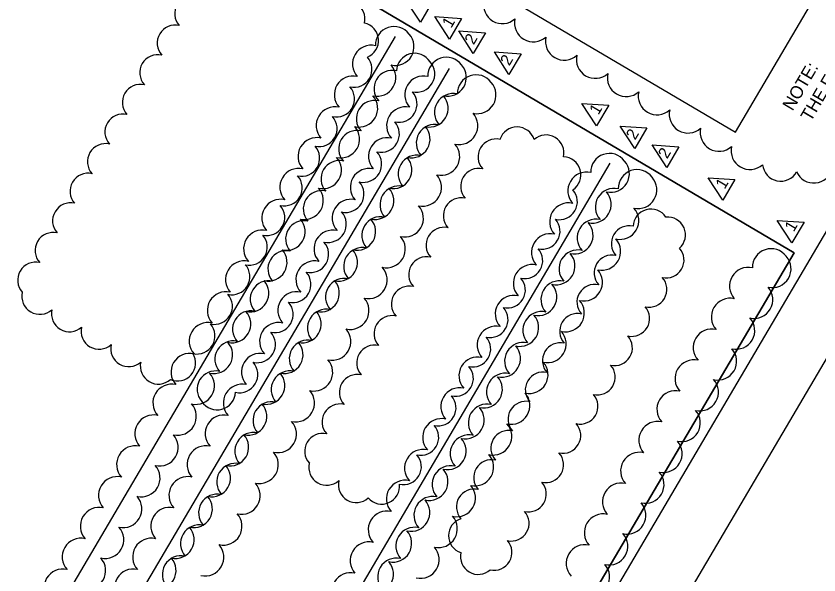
# Model space of a CAD drawing. Extents: x 12 to 1151523, y -64 to 610812.
# Drawn here: x 1151171.991 to 1151172.624, y 610616.177 to 610616.617 of the extents above; entities that cross this region are included whole.
import ezdxf

# ---------------------------------------------------------------- set-up
doc = ezdxf.new("R2010")
doc.units = 0
for name, color, linetype in [('ANNOTATION', 7, 'Continuous'), ('BANNOTATION', 7, 'Continuous'), ('BORDER', 7, 'Continuous'), ('DIMENSIONS', 7, 'Continuous'), ('PLOT BOUNDARY', 7, 'Continuous')]:
    doc.layers.add(name, color=color, linetype=linetype)

msp = doc.modelspace()

# ---------------------------------------------------------------- linework, layer by layer
at = {"layer": 'ANNOTATION'}
for p, q in [((1151171.68443, 610615.57233), (1151172.29045, 610616.60119)), ((1151171.72712, 610615.54719), (1151172.33313, 610616.57605)), ((1151171.85385, 610615.47254), (1151172.45987, 610616.5014))]:
    msp.add_line(p, q, dxfattribs=at)
for points in [[(1151172.55849, 610616.52572), (1151173.14334, 610617.51864), (1151172.53973, 610617.87417), (1151171.95488, 610616.88126)], [(1151170.49753, 610616.26298), (1151171.11366, 610617.30901), (1151172.60473, 610616.43074), (1151171.9886, 610615.38471)], [(1151171.9886, 610615.38471), (1151172.60473, 610616.43074), (1151171.11366, 610617.30901), (1151170.49753, 610616.26298)]]:
    msp.add_lwpolyline(points, close=True, dxfattribs=at)
for centre, radius, start, end in [((1151172.13056, 610616.61929), 0.01421, 77.0011, 222.0011), ((1151172.25215, 610616.61496), 0.01421, 347.0011, 132.0011), ((1151172.37476, 610616.62612), 0.01485, 167.0011, 312.0011), ((1151172.37476, 610616.62612), 0.01485, 167.0011, 312.0011), ((1151172.2629, 610616.59791), 0.0142, 292.39822, 77.39822), ((1151172.39916, 610616.61175), 0.01485, 167.0011, 312.0011), ((1151172.39916, 610616.61175), 0.01485, 167.0011, 312.0011), ((1151172.11681, 610616.59594), 0.01421, 77.0011, 222.0011), ((1151172.28941, 610616.59427), 0.01476, 36.35963, 181.35963), ((1151172.29032, 610616.59313), 0.01478, 257.0011, 42.0011), ((1151172.42356, 610616.59738), 0.01485, 167.0011, 312.0011), ((1151172.42356, 610616.59738), 0.01485, 167.0011, 312.0011), ((1151172.27133, 610616.57952), 0.01478, 77.0011, 222.0011), ((1151172.10305, 610616.57259), 0.01421, 77.0011, 222.0011), ((1151172.30564, 610616.57351), 0.0144, 32.75613, 177.75613), ((1151172.44796, 610616.58301), 0.01485, 167.0011, 312.0011), ((1151172.44796, 610616.58301), 0.01485, 167.0011, 312.0011), ((1151172.25775, 610616.57528), 0.01421, 257.0011, 42.0011), ((1151172.30704, 610616.57165), 0.01441, 257.0011, 42.0011), ((1151172.33065, 610616.56998), 0.01476, 36.35963, 181.35963), ((1151172.27602, 610616.56885), 0.01478, 257.0011, 42.0011), ((1151172.288, 610616.56003), 0.01441, 77.0011, 222.0011), ((1151172.33156, 610616.56884), 0.01478, 257.0011, 42.0011), ((1151172.25702, 610616.55524), 0.01478, 77.0011, 222.0011), ((1151172.31257, 610616.55523), 0.01478, 77.0011, 222.0011), ((1151172.35404, 610616.5562), 0.01476, 36.35963, 181.35963), ((1151172.47236, 610616.56863), 0.01485, 167.0011, 312.0011), ((1151172.47236, 610616.56863), 0.01485, 167.0011, 312.0011), ((1151172.0893, 610616.54924), 0.01421, 77.0011, 222.0011), ((1151172.24399, 610616.55193), 0.01421, 257.0011, 42.0011), ((1151172.35495, 610616.55507), 0.01478, 257.0011, 42.0011), ((1151172.26171, 610616.54456), 0.01478, 257.0011, 42.0011), ((1151172.29309, 610616.54797), 0.01441, 257.0011, 42.0011), ((1151172.31726, 610616.54456), 0.01478, 257.0011, 42.0011), ((1151172.33596, 610616.54145), 0.01478, 77.0011, 222.0011), ((1151172.49676, 610616.55426), 0.01485, 167.0011, 312.0011), ((1151172.49676, 610616.55426), 0.01485, 167.0011, 312.0011), ((1151172.27405, 610616.53634), 0.01441, 77.0011, 222.0011), ((1151172.24272, 610616.53095), 0.01478, 77.0011, 222.0011), ((1151172.29826, 610616.53094), 0.01478, 77.0011, 222.0011), ((1151172.52116, 610616.53989), 0.01485, 167.0011, 312.0011), ((1151172.52116, 610616.53989), 0.01485, 167.0011, 312.0011), ((1151172.07554, 610616.52588), 0.01421, 77.0011, 222.0011), ((1151172.23024, 610616.52857), 0.01421, 257.0011, 42.0011), ((1151172.34064, 610616.53078), 0.01478, 257.0011, 42.0011), ((1151172.24741, 610616.52028), 0.01478, 257.0011, 42.0011), ((1151172.27914, 610616.52428), 0.01441, 257.0011, 42.0011), ((1151172.30295, 610616.52027), 0.01478, 257.0011, 42.0011), ((1151172.32165, 610616.51717), 0.01478, 77.0011, 222.0011), ((1151172.38633, 610616.51574), 0.01411, 17.24342, 162.24342), ((1151172.54556, 610616.52552), 0.01485, 167.0011, 312.0011), ((1151172.54556, 610616.52552), 0.01485, 167.0011, 312.0011), ((1151172.55265, 610616.53034), 0.02161, 183.93653357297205, 183.93653379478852), ((1151172.2601, 610616.51265), 0.01441, 77.0011, 222.0011), ((1151172.40925, 610616.50943), 0.01412, 347.0011, 132.0011), ((1151172.06179, 610616.50253), 0.01421, 77.0011, 222.0011), ((1151172.22841, 610616.50667), 0.01478, 77.0011, 222.0011), ((1151172.28396, 610616.50666), 0.01478, 77.0011, 222.0011), ((1151172.32634, 610616.5065), 0.01478, 257.0011, 42.0011), ((1151172.36972, 610616.50629), 0.01412, 77.0011, 222.0011), ((1151172.21648, 610616.50522), 0.01421, 257.0011, 42.0011), ((1151172.26518, 610616.50059), 0.01441, 257.0011, 42.0011), ((1151172.56996, 610616.51115), 0.01485, 167.0011, 312.0011), ((1151172.56996, 610616.51115), 0.01485, 167.0011, 312.0011), ((1151172.2331, 610616.49599), 0.01478, 257.0011, 42.0011), ((1151172.24615, 610616.48896), 0.01441, 77.0011, 222.0011), ((1151172.28865, 610616.49599), 0.01478, 257.0011, 42.0011), ((1151172.30735, 610616.49288), 0.01478, 77.0011, 222.0011), ((1151172.42256, 610616.49214), 0.01412, 303.19854, 88.19854), ((1151172.45922, 610616.49425), 0.01476, 36.35963, 181.35963), ((1151172.21411, 610616.48238), 0.01478, 77.0011, 222.0011), ((1151172.26965, 610616.48237), 0.01478, 77.0011, 222.0011), ((1151172.35605, 610616.48308), 0.01412, 77.0011, 222.0011), ((1151172.46013, 610616.49312), 0.01478, 257.0011, 42.0011), ((1151172.59423, 610616.50157), 0.01441, 185.78345, 330.78345), ((1151172.59423, 610616.50157), 0.01441, 185.78345, 330.78345), ((1151172.62038, 610616.50051), 0.01484, 203.75334, 346.71427), ((1151172.04803, 610616.47918), 0.01421, 77.0011, 222.0011), ((1151172.20273, 610616.48187), 0.01421, 257.0011, 42.0011), ((1151172.31204, 610616.48221), 0.01478, 257.0011, 42.0011), ((1151172.44113, 610616.4795), 0.01478, 77.0011, 222.0011), ((1151172.48094, 610616.48146), 0.01476, 36.35963, 181.35963), ((1151172.62601, 610616.48509), 0.0214, 153.80626168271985, 153.8062619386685), ((1151172.25123, 610616.47691), 0.01441, 257.0011, 42.0011), ((1151172.48184, 610616.48032), 0.01478, 257.0011, 42.0011), ((1151172.2188, 610616.47171), 0.01478, 257.0011, 42.0011), ((1151172.2322, 610616.46528), 0.01441, 77.0011, 222.0011), ((1151172.27434, 610616.4717), 0.01478, 257.0011, 42.0011), ((1151172.29304, 610616.4686), 0.01478, 77.0011, 222.0011), ((1151172.4198, 610616.47088), 0.01412, 257.0011, 42.0011), ((1151172.44582, 610616.46883), 0.01478, 257.0011, 42.0011), ((1151172.46285, 610616.46671), 0.01478, 77.0011, 222.0011), ((1151172.1998, 610616.45809), 0.01478, 77.0011, 222.0011), ((1151172.25535, 610616.45809), 0.01478, 77.0011, 222.0011), ((1151172.34238, 610616.45988), 0.01412, 77.0011, 222.0011), ((1151172.03428, 610616.45583), 0.01421, 77.0011, 222.0011), ((1151172.18897, 610616.45851), 0.01421, 257.0011, 42.0011), ((1151172.29773, 610616.45793), 0.01478, 257.0011, 42.0011), ((1151172.42683, 610616.45522), 0.01478, 77.0011, 222.0011), ((1151172.46754, 610616.45604), 0.01478, 257.0011, 42.0011), ((1151172.23728, 610616.45322), 0.01441, 257.0011, 42.0011), ((1151172.27874, 610616.44431), 0.01478, 77.0011, 222.0011), ((1151172.49189, 610616.45111), 0.01403, 33.0718, 178.0718), ((1151172.20449, 610616.44742), 0.01478, 257.0011, 42.0011), ((1151172.21824, 610616.44159), 0.01441, 77.0011, 222.0011), ((1151172.26004, 610616.44742), 0.01478, 257.0011, 42.0011), ((1151172.40613, 610616.44768), 0.01412, 257.0011, 42.0011), ((1151172.43152, 610616.44455), 0.01478, 257.0011, 42.0011), ((1151172.44855, 610616.44242), 0.01478, 77.0011, 222.0011), ((1151172.50518, 610616.44483), 0.01401, 311.28305, 96.28305), ((1151172.02052, 610616.43247), 0.01421, 77.0011, 222.0011), ((1151172.1855, 610616.43381), 0.01478, 77.0011, 222.0011), ((1151172.24104, 610616.4338), 0.01478, 77.0011, 222.0011), ((1151172.32872, 610616.43667), 0.01412, 77.0011, 222.0011), ((1151172.47472, 610616.43792), 0.01402, 77.0011, 222.0011), ((1151172.17522, 610616.43516), 0.01421, 257.0011, 42.0011), ((1151172.28343, 610616.43364), 0.01478, 257.0011, 42.0011), ((1151172.41252, 610616.43093), 0.01478, 77.0011, 222.0011), ((1151172.45324, 610616.43175), 0.01478, 257.0011, 42.0011), ((1151172.22333, 610616.42953), 0.01441, 257.0011, 42.0011), ((1151172.26443, 610616.42003), 0.01478, 77.0011, 222.0011), ((1151172.39247, 610616.42447), 0.01412, 257.0011, 42.0011), ((1151172.504, 610616.42492), 0.01402, 257.0011, 42.0011), ((1151172.5867, 610616.41916), 0.01476, 36.35963, 181.35963), ((1151172.19019, 610616.42314), 0.01478, 257.0011, 42.0011), ((1151172.20429, 610616.4179), 0.01441, 77.0011, 222.0011), ((1151172.24573, 610616.42313), 0.01478, 257.0011, 42.0011), ((1151172.31505, 610616.41347), 0.01412, 77.0011, 222.0011), ((1151172.41721, 610616.42026), 0.01478, 257.0011, 42.0011), ((1151172.43424, 610616.41814), 0.01478, 77.0011, 222.0011), ((1151172.46114, 610616.41487), 0.01402, 77.0011, 222.0011), ((1151172.58761, 610616.41802), 0.01478, 257.0011, 42.0011), ((1151172.00677, 610616.40912), 0.01421, 77.0011, 222.0011), ((1151172.1712, 610616.40952), 0.01478, 77.0011, 222.0011), ((1151172.16146, 610616.41181), 0.01421, 257.0011, 42.0011), ((1151172.22674, 610616.40952), 0.01478, 77.0011, 222.0011), ((1151172.39822, 610616.40665), 0.01478, 77.0011, 222.0011), ((1151172.20938, 610616.40584), 0.01441, 257.0011, 42.0011), ((1151172.26912, 610616.40936), 0.01478, 257.0011, 42.0011), ((1151172.43893, 610616.40747), 0.01478, 257.0011, 42.0011), ((1151172.56862, 610616.40441), 0.01478, 77.0011, 222.0011), ((1151172.17588, 610616.39885), 0.01478, 257.0011, 42.0011), ((1151172.19034, 610616.39422), 0.01441, 77.0011, 222.0011), ((1151172.23143, 610616.39885), 0.01478, 257.0011, 42.0011), ((1151172.25013, 610616.39574), 0.01478, 77.0011, 222.0011), ((1151172.3788, 610616.40127), 0.01412, 257.0011, 42.0011), ((1151172.41994, 610616.39385), 0.01478, 77.0011, 222.0011), ((1151172.49043, 610616.40188), 0.01402, 257.0011, 42.0011), ((1151172.30138, 610616.39026), 0.01412, 77.0011, 222.0011), ((1151172.40291, 610616.39597), 0.01478, 257.0011, 42.0011), ((1151172.44757, 610616.39183), 0.01402, 77.0011, 222.0011), ((1151172.57331, 610616.39374), 0.01478, 257.0011, 42.0011), ((1151172.01005, 610616.39642), 0.01421, 167.0011, 312.0011), ((1151172.15689, 610616.38524), 0.01478, 77.0011, 222.0011), ((1151172.14771, 610616.38846), 0.01421, 257.0011, 42.0011), ((1151172.21244, 610616.38523), 0.01478, 77.0011, 222.0011), ((1151172.38392, 610616.38236), 0.01478, 77.0011, 222.0011), ((1151172.19542, 610616.38216), 0.01441, 257.0011, 42.0011), ((1151172.25482, 610616.38507), 0.01478, 257.0011, 42.0011), ((1151172.42463, 610616.38318), 0.01478, 257.0011, 42.0011), ((1151172.55432, 610616.38012), 0.01478, 77.0011, 222.0011), ((1151172.0334, 610616.38266), 0.01421, 167.0011, 312.0011), ((1151172.16158, 610616.37457), 0.01478, 257.0011, 42.0011), ((1151172.17639, 610616.37053), 0.01441, 77.0011, 222.0011), ((1151172.21712, 610616.37456), 0.01478, 257.0011, 42.0011), ((1151172.23582, 610616.37146), 0.01478, 77.0011, 222.0011), ((1151172.36513, 610616.37806), 0.01412, 257.0011, 42.0011), ((1151172.40563, 610616.36957), 0.01478, 77.0011, 222.0011), ((1151172.47685, 610616.37883), 0.01402, 257.0011, 42.0011), ((1151172.28771, 610616.36706), 0.01412, 77.0011, 222.0011), ((1151172.3886, 610616.37169), 0.01478, 257.0011, 42.0011), ((1151172.434, 610616.36878), 0.01402, 77.0011, 222.0011), ((1151172.559, 610616.36945), 0.01478, 257.0011, 42.0011), ((1151172.05676, 610616.36891), 0.01421, 167.0011, 312.0011), ((1151172.14259, 610616.36095), 0.01478, 77.0011, 222.0011), ((1151172.13395, 610616.3651), 0.01421, 257.0011, 42.0011), ((1151172.19813, 610616.36095), 0.01478, 77.0011, 222.0011), ((1151172.24051, 610616.36078), 0.01478, 257.0011, 42.0011), ((1151172.36961, 610616.35808), 0.01478, 77.0011, 222.0011), ((1151172.54001, 610616.35584), 0.01478, 77.0011, 222.0011), ((1151172.18147, 610616.35847), 0.01441, 257.0011, 42.0011), ((1151172.35146, 610616.35486), 0.01412, 257.0011, 42.0011), ((1151172.41032, 610616.3589), 0.01478, 257.0011, 42.0011), ((1151172.46328, 610616.35579), 0.01402, 257.0011, 42.0011), ((1151172.08011, 610616.35515), 0.01421, 167.0011, 312.0011), ((1151172.14727, 610616.35028), 0.01478, 257.0011, 42.0011), ((1151172.16243, 610616.34684), 0.01441, 77.0011, 222.0011), ((1151172.20282, 610616.35028), 0.01478, 257.0011, 42.0011), ((1151172.22152, 610616.34717), 0.01478, 77.0011, 222.0011), ((1151172.27404, 610616.34385), 0.01412, 77.0011, 222.0011), ((1151172.39133, 610616.34528), 0.01478, 77.0011, 222.0011), ((1151172.42042, 610616.34574), 0.01402, 77.0011, 222.0011), ((1151172.12828, 610616.33667), 0.01478, 77.0011, 222.0011), ((1151172.18383, 610616.33666), 0.01478, 77.0011, 222.0011), ((1151172.3743, 610616.3474), 0.01478, 257.0011, 42.0011), ((1151172.5447, 610616.34517), 0.01478, 257.0011, 42.0011), ((1151172.11864, 610616.34385), 0.0142, 246.44677, 31.44677), ((1151172.22621, 610616.3365), 0.01478, 257.0011, 42.0011), ((1151172.35531, 610616.33379), 0.01478, 77.0011, 222.0011), ((1151172.52571, 610616.33155), 0.01478, 77.0011, 222.0011), ((1151172.10346, 610616.3414), 0.01421, 167.0011, 312.0011), ((1151172.16752, 610616.33478), 0.01441, 257.0011, 42.0011), ((1151172.33779, 610616.33165), 0.01412, 257.0011, 42.0011), ((1151172.39602, 610616.33461), 0.01478, 257.0011, 42.0011), ((1151172.44971, 610616.33274), 0.01402, 257.0011, 42.0011), ((1151172.13297, 610616.326), 0.01478, 257.0011, 42.0011), ((1151172.14848, 610616.32315), 0.01441, 77.0011, 222.0011), ((1151172.18851, 610616.32599), 0.01478, 257.0011, 42.0011), ((1151172.20722, 610616.32289), 0.01478, 77.0011, 222.0011), ((1151172.26038, 610616.32065), 0.01412, 77.0011, 222.0011), ((1151172.35999, 610616.32312), 0.01478, 257.0011, 42.0011), ((1151172.37702, 610616.321), 0.01478, 77.0011, 222.0011), ((1151172.40685, 610616.32269), 0.01402, 77.0011, 222.0011), ((1151172.11398, 610616.31238), 0.01478, 77.0011, 222.0011), ((1151172.16952, 610616.31238), 0.01478, 77.0011, 222.0011), ((1151172.53039, 610616.32088), 0.01478, 257.0011, 42.0011), ((1151172.14988, 610616.3213), 0.0144, 212.75613, 357.75613), ((1151172.2119, 610616.31221), 0.01478, 257.0011, 42.0011), ((1151172.341, 610616.30951), 0.01478, 77.0011, 222.0011), ((1151172.38171, 610616.31033), 0.01478, 257.0011, 42.0011), ((1151172.5114, 610616.30727), 0.01478, 77.0011, 222.0011), ((1151172.32412, 610616.30845), 0.01412, 257.0011, 42.0011), ((1151172.39327, 610616.29965), 0.01402, 77.0011, 222.0011), ((1151172.43613, 610616.3097), 0.01402, 257.0011, 42.0011), ((1151172.11867, 610616.30171), 0.01478, 257.0011, 42.0011), ((1151172.17421, 610616.30171), 0.01478, 257.0011, 42.0011), ((1151172.19291, 610616.2986), 0.01478, 77.0011, 222.0011), ((1151172.24671, 610616.29744), 0.01412, 77.0011, 222.0011), ((1151172.34569, 610616.29883), 0.01478, 257.0011, 42.0011), ((1151172.36272, 610616.29671), 0.01478, 77.0011, 222.0011), ((1151172.09967, 610616.2881), 0.01478, 77.0011, 222.0011), ((1151172.15522, 610616.28809), 0.01478, 77.0011, 222.0011), ((1151172.51609, 610616.2966), 0.01478, 257.0011, 42.0011), ((1151172.1976, 610616.28793), 0.01478, 257.0011, 42.0011), ((1151172.31046, 610616.28524), 0.01412, 257.0011, 42.0011), ((1151172.3267, 610616.28522), 0.01478, 77.0011, 222.0011), ((1151172.36741, 610616.28604), 0.01478, 257.0011, 42.0011), ((1151172.42256, 610616.28666), 0.01402, 257.0011, 42.0011), ((1151172.4971, 610616.28298), 0.01478, 77.0011, 222.0011), ((1151172.17861, 610616.27432), 0.01478, 77.0011, 222.0011), ((1151172.23304, 610616.27424), 0.01412, 77.0011, 222.0011), ((1151172.3797, 610616.2766), 0.01402, 77.0011, 222.0011), ((1151172.10436, 610616.27743), 0.01478, 257.0011, 42.0011), ((1151172.15991, 610616.27742), 0.01478, 257.0011, 42.0011), ((1151172.33139, 610616.27455), 0.01478, 257.0011, 42.0011), ((1151172.34842, 610616.27243), 0.01478, 77.0011, 222.0011), ((1151172.50179, 610616.27231), 0.01478, 257.0011, 42.0011), ((1151172.08537, 610616.26381), 0.01478, 77.0011, 222.0011), ((1151172.14091, 610616.26381), 0.01478, 77.0011, 222.0011), ((1151172.31239, 610616.26093), 0.01478, 77.0011, 222.0011), ((1151172.18329, 610616.26364), 0.01478, 257.0011, 42.0011), ((1151172.29679, 610616.26204), 0.01412, 257.0011, 42.0011), ((1151172.3531, 610616.26176), 0.01478, 257.0011, 42.0011), ((1151172.40899, 610616.26361), 0.01402, 257.0011, 42.0011), ((1151172.48279, 610616.2587), 0.01478, 77.0011, 222.0011), ((1151172.09006, 610616.25314), 0.01478, 257.0011, 42.0011), ((1151172.1456, 610616.25313), 0.01478, 257.0011, 42.0011), ((1151172.1643, 610616.25003), 0.01478, 77.0011, 222.0011), ((1151172.2363, 610616.26161), 0.01412, 167.0011, 312.0011), ((1151172.33411, 610616.24814), 0.01478, 77.0011, 222.0011), ((1151172.36613, 610616.25356), 0.01402, 77.0011, 222.0011), ((1151172.31708, 610616.25026), 0.01478, 257.0011, 42.0011), ((1151172.48748, 610616.24803), 0.01478, 257.0011, 42.0011), ((1151172.07106, 610616.23953), 0.01478, 77.0011, 222.0011), ((1151172.12661, 610616.23952), 0.01478, 77.0011, 222.0011), ((1151172.25951, 610616.24795), 0.01412, 167.0011, 312.0011), ((1151172.29809, 610616.23665), 0.01478, 77.0011, 222.0011), ((1151172.16899, 610616.23936), 0.01478, 257.0011, 42.0011), ((1151172.27958, 610616.24675), 0.01412, 221.20772, 6.20772), ((1151172.3388, 610616.23747), 0.01478, 257.0011, 42.0011), ((1151172.35255, 610616.23052), 0.01402, 77.0011, 222.0011), ((1151172.39541, 610616.24057), 0.01402, 257.0011, 42.0011), ((1151172.46849, 610616.23441), 0.01478, 77.0011, 222.0011), ((1151172.07575, 610616.22886), 0.01478, 257.0011, 42.0011), ((1151172.1313, 610616.22885), 0.01478, 257.0011, 42.0011), ((1151172.15, 610616.22574), 0.01478, 77.0011, 222.0011), ((1151172.31981, 610616.22386), 0.01478, 77.0011, 222.0011), ((1151172.30278, 610616.22598), 0.01478, 257.0011, 42.0011), ((1151172.47318, 610616.22374), 0.01478, 257.0011, 42.0011), ((1151172.05676, 610616.21524), 0.01478, 77.0011, 222.0011), ((1151172.1123, 610616.21524), 0.01478, 77.0011, 222.0011), ((1151172.15469, 610616.21507), 0.01478, 257.0011, 42.0011), ((1151172.28378, 610616.21236), 0.01478, 77.0011, 222.0011), ((1151172.38184, 610616.21752), 0.01402, 257.0011, 42.0011), ((1151172.45418, 610616.21013), 0.01478, 77.0011, 222.0011), ((1151172.32449, 610616.21318), 0.01478, 257.0011, 42.0011), ((1151172.34632, 610616.20775), 0.01402, 107.35788, 252.35788), ((1151172.06145, 610616.20457), 0.01478, 257.0011, 42.0011), ((1151172.11699, 610616.20456), 0.01478, 257.0011, 42.0011), ((1151172.13569, 610616.20146), 0.01478, 77.0011, 222.0011), ((1151172.3055, 610616.19957), 0.01478, 77.0011, 222.0011), ((1151172.28847, 610616.20169), 0.01478, 257.0011, 42.0011), ((1151172.45887, 610616.19946), 0.01478, 257.0011, 42.0011), ((1151172.04245, 610616.19096), 0.01478, 77.0011, 222.0011), ((1151172.098, 610616.19095), 0.01478, 77.0011, 222.0011), ((1151172.14038, 610616.19079), 0.01478, 257.0011, 42.0011), ((1151172.26948, 610616.18808), 0.01478, 77.0011, 222.0011), ((1151172.36827, 610616.19448), 0.01402, 257.0011, 42.0011), ((1151172.43988, 610616.18584), 0.01478, 77.0011, 222.0011), ((1151172.31019, 610616.1889), 0.01478, 257.0011, 42.0011), ((1151172.35573, 610616.19124), 0.01402, 167.0011, 312.0011), ((1151172.04714, 610616.18028), 0.01478, 257.0011, 42.0011), ((1151172.10269, 610616.18028), 0.01478, 257.0011, 42.0011), ((1151172.12139, 610616.17717), 0.01478, 77.0011, 222.0011), ((1151172.27417, 610616.17741), 0.01478, 257.0011, 42.0011), ((1151172.2912, 610616.17529), 0.01478, 77.0011, 222.0011), ((1151172.02815, 610616.16667), 0.01478, 77.0011, 222.0011), ((1151172.0837, 610616.16666), 0.01478, 77.0011, 222.0011), ((1151172.44457, 610616.17517), 0.01478, 257.0011, 42.0011), ((1151172.25517, 610616.16379), 0.01478, 77.0011, 222.0011)]:
    msp.add_arc(centre, radius, start, end, dxfattribs=at)
at = {"layer": 'BORDER'}
msp.add_line((1151171.99415, 610615.36768), (1151173.34754, 610617.66538), dxfattribs=at)
at = {"layer": 'DIMENSIONS'}
for p, q in [((1151172.31969, 610616.62872), (1151172.31009, 610616.61243)), ((1151172.34254, 610616.61535), (1151172.33295, 610616.59906)), ((1151172.36141, 610616.60415), (1151172.35181, 610616.58786)), ((1151172.38952, 610616.58759), (1151172.37992, 610616.5713)), ((1151172.45863, 610616.54697), (1151172.44904, 610616.53068)), ((1151172.48875, 610616.52914), (1151172.47916, 610616.51285)), ((1151172.514, 610616.51427), (1151172.5044, 610616.49798)), ((1151172.55814, 610616.48836), (1151172.54854, 610616.47207)), ((1151172.61264, 610616.45478), (1151172.60305, 610616.43849))]:
    msp.add_line(p, q, dxfattribs=at)
for points in [[(1151172.31009, 610616.61243), (1151172.2986, 610616.63017), (1151172.31969, 610616.62872)], [(1151172.33295, 610616.59906), (1151172.32145, 610616.6168), (1151172.34254, 610616.61535)], [(1151172.35181, 610616.58786), (1151172.34032, 610616.6056), (1151172.36141, 610616.60415)], [(1151172.37992, 610616.5713), (1151172.36843, 610616.58904), (1151172.38952, 610616.58759)], [(1151172.44904, 610616.53068), (1151172.43755, 610616.54842), (1151172.45863, 610616.54697)], [(1151172.47916, 610616.51285), (1151172.46767, 610616.53059), (1151172.48875, 610616.52914)], [(1151172.5044, 610616.49798), (1151172.49291, 610616.51572), (1151172.514, 610616.51427)], [(1151172.54854, 610616.47207), (1151172.53705, 610616.48981), (1151172.55814, 610616.48836)], [(1151172.60305, 610616.43849), (1151172.59155, 610616.45623), (1151172.61264, 610616.45478)]]:
    msp.add_lwpolyline(points, dxfattribs=at)
at = {"layer": 'PLOT BOUNDARY'}
msp.add_lwpolyline([(1151171.96962, 610615.22558), (1151173.4076, 610617.66689), (1151171.82793, 610618.59734), (1151170.38995, 610616.15603)], close=True, dxfattribs=at)

# ---------------------------------------------------------------- texts
at = {"layer": 'BANNOTATION'}
for s, p in [('THE EARTHWORK SUMMARY ASSUMES THE NORTHBOUND WORK IS COMPLETED FIRST, FOLLOWED BY THE ', (1151172.61798, 610616.53344)), ('NOTE:', (1151172.60359, 610616.54192))]:
    msp.add_text(s, height=0.01, rotation=59.5011, dxfattribs=at).set_placement(p)
at = {"layer": 'DIMENSIONS'}
for s, p in [('1', (1151172.3344, 610616.60723)), ('2', (1151172.35212, 610616.59409)), ('2', (1151172.38023, 610616.57753)), ('1', (1151172.45049, 610616.53885)), ('2', (1151172.47947, 610616.51908)), ('2', (1151172.50472, 610616.50421)), ('1', (1151172.55, 610616.48024)), ('1', (1151172.6045, 610616.44666))]:
    msp.add_text(s, height=0.00907, rotation=59.5011, dxfattribs=at).set_placement(p)

doc.saveas('drawing.dxf')
